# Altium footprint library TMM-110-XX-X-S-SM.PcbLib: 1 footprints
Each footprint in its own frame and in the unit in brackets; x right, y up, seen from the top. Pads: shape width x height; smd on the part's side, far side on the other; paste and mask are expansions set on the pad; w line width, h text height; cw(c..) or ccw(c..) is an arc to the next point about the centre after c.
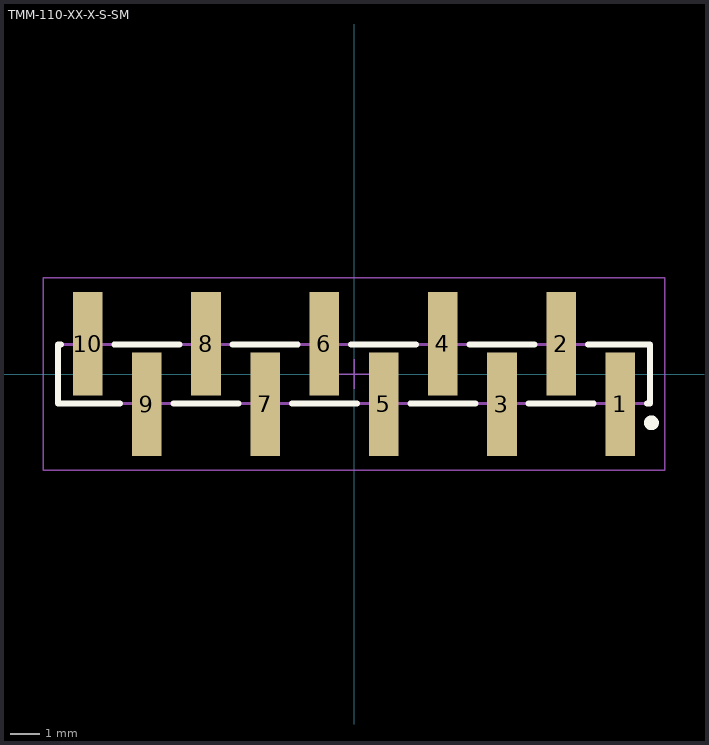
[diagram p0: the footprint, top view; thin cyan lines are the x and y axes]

## TMM-110-XX-X-S-SM [mm]
pads (10):
  rect 1x3.5 smd mask+0: 1(9,-1.016) 2(7,1.016) 3(5,-1.016) 4(3,1.016) 5(1,-1.016) 6(-1,1.016) 7(-3,-1.016) 8(-5,1.016) 9(-7,-1.016) 10(-9,1.016)
Top Overlay:
  circle w0.25: c10.05,-1.65 r0.125
  lines w0.2: -9.9,1 -10,1 -10,-1 -7.9,-1 ; -8.1,1 -5.9,1 ; -6.1,-1 -3.9,-1 ; -4.1,1 -1.9,1 ; -2.1,-1 0.1,-1 ; -0.1,1 2.1,1 ; 1.9,-1 4.1,-1 ; 3.9,1 6.1,1 ; 5.9,-1 8.1,-1 ; 7.9,1 10,1 10,-1 9.9,-1
Mechanical 12:
  lines w0.001: -10,-1 10,-1 10,1 -10,1 -10,-1
Mechanical 13:
  lines w0.1: -10,-1 10,-1 10,1 -10,1 -10,-1
  text ".Designator" at 0,-0.127 h1.52
Mechanical 15:
  lines w0.05: -0.5,0 0.5,0 ; 0,-0.5 0,0.5 ; -10.5,-3.25 10.5,-3.25 10.5,3.25 -10.5,3.25 -10.5,-3.25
